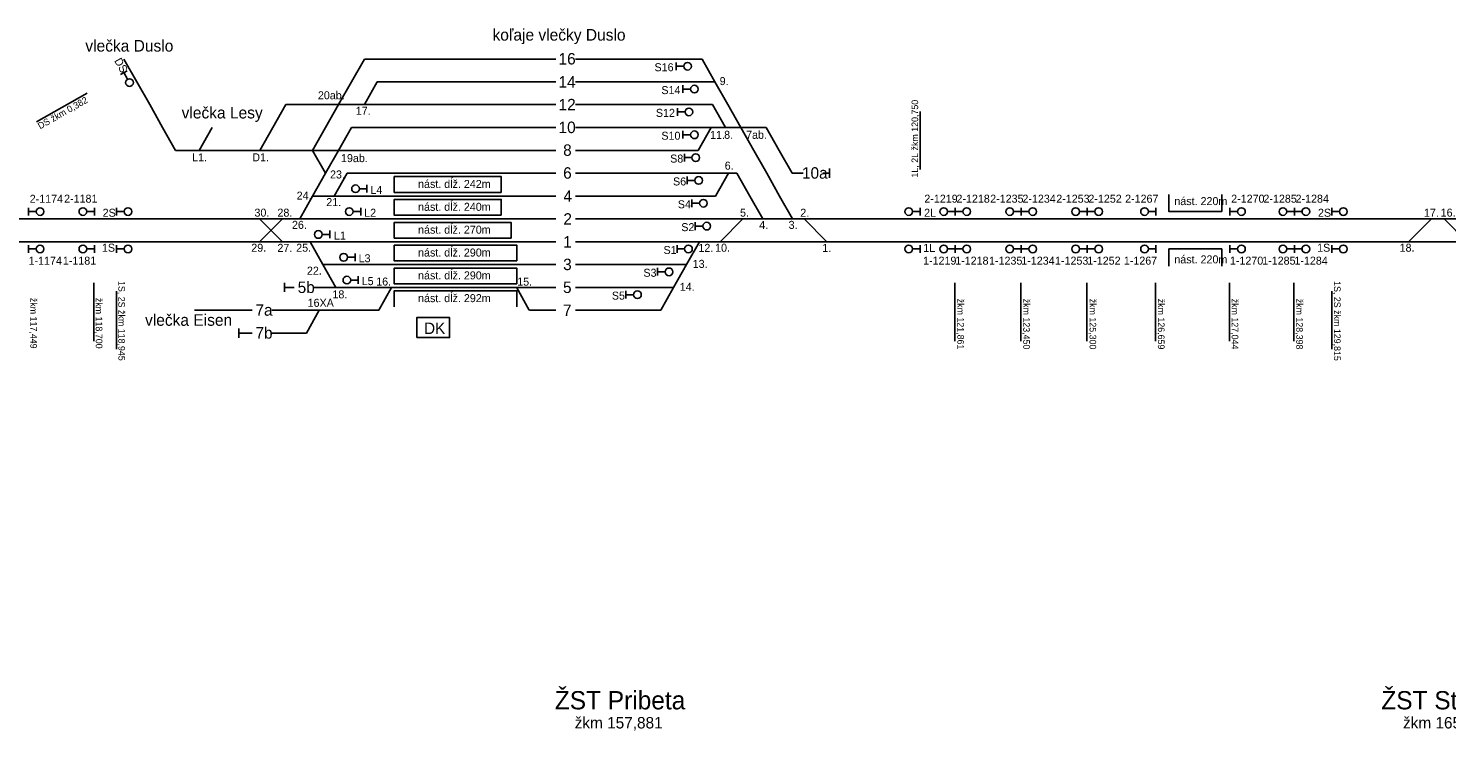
# Model space of a CAD drawing. Extents: x -119 to 851, y -238 to 59.
# Drawn here: x 119.9 to 243.9, y -152.1 to -90.6 of the extents above; entities that cross this region are included whole.
import ezdxf

# ---------------------------------------------------------------- set-up
doc = ezdxf.new("R2010")
doc.units = 0
for name, color, linetype in [('budova', 7, 'Continuous'), ('Level 2', 7, 'Continuous'), ('nastupistia', 7, 'Continuous'), ('netlač', 7, 'Continuous'), ('popisky navestidla', 7, 'Continuous'), ('popisky stanic a zastavok', 7, 'Continuous'), ('PU_navestidla', 7, 'Continuous'), ('PU_oznacenie navestidiel', 7, 'Continuous'), ('PU_stan_kolaje', 7, 'Continuous'), ('PU_vlecky', 7, 'Continuous')]:
    doc.layers.add(name, color=color, linetype=linetype)

msp = doc.modelspace()

# ---------------------------------------------------------------- linework, layer by layer
at = {"layer": 'budova'}
msp.add_lwpolyline([(153.86, -117.69), (156.73, -117.69), (156.73, -115.94), (153.86, -115.94)], close=True, dxfattribs=at)
at = {"layer": 'Level 2'}
for p, q in [((189.96, -103.71), (189.96, -102.91)), ((144.75, -105.31), (166.03, -105.31)), ((167.75, -105.31), (179.98, -105.31)), ((127.6, -107.3), (134.86, -107.3)), ((134.86, -107.3), (151.05, -107.3)), ((151.05, -107.3), (166.03, -107.3)), ((167.75, -107.3), (174.65, -107.3)), ((174.65, -107.3), (197.85, -107.3)), ((233.89, -107.3), (243.69, -107.3)), ((243.69, -107.3), (259.89, -107.3)), ((127.6, -109.3), (149.85, -109.3)), ((149.85, -109.3), (166.03, -109.3)), ((167.75, -109.3), (175.65, -109.3)), ((175.65, -109.3), (193.95, -109.3)), ((193.95, -109.3), (197.85, -109.3)), ((233.89, -109.3), (258.69, -109.3)), ((145.65, -111.3), (166.03, -111.3)), ((167.75, -111.3), (177.45, -111.3)), ((142.3, -113.7), (142.3, -112.9)), ((167.75, -113.3), (176.32, -113.3)), ((167.75, -115.3), (175.19, -115.3)), ((138.29, -117.7), (138.29, -116.9))]:
    msp.add_line(p, q, dxfattribs=at)
at = {"layer": 'nastupistia'}
for points in [[(161.24, -104.99), (151.89, -104.99), (151.89, -103.61), (161.24, -103.61)], [(161.25, -106.99), (151.89, -106.99), (151.89, -105.61), (161.25, -105.61)], [(162.11, -108.99), (151.89, -108.99), (151.89, -107.61), (162.11, -107.61)], [(162.61, -110.99), (151.89, -110.99), (151.89, -109.61), (162.61, -109.61)], [(162.6, -112.99), (151.89, -112.99), (151.89, -111.61), (162.6, -111.61)]]:
    msp.add_lwpolyline(points, close=True, dxfattribs=at)
for points in [[(219.64, -105.17), (219.64, -106.67), (224.27, -106.67), (224.27, -105.17)], [(219.64, -111.44), (219.64, -109.94), (224.27, -109.94), (224.27, -111.44)], [(151.89, -114.99), (151.89, -113.6), (162.61, -113.6), (162.61, -114.99)]]:
    msp.add_lwpolyline(points, dxfattribs=at)
at = {"layer": 'netlač'}
for p, q in [((149.27, -93.32), (166.03, -93.32)), ((178.81, -93.32), (167.75, -93.32)), ((150.4, -95.31), (166.03, -95.31)), ((179.94, -95.31), (167.75, -95.31)), ((149.27, -97.31), (142.4, -97.31)), ((149.27, -97.31), (166.03, -97.31)), ((179.72, -97.31), (167.75, -97.31)), ((148.14, -99.31), (166.03, -99.31)), ((182.2, -99.31), (167.75, -99.31)), ((182.2, -99.31), (184.42, -99.31)), ((147.01, -101.31), (132.76, -101.31)), ((147.01, -101.31), (166.03, -101.31)), ((178.47, -101.31), (167.75, -101.31)), ((147.76, -103.31), (166.03, -103.31)), ((181.86, -103.31), (167.75, -103.31)), ((186.68, -103.31), (187.64, -103.31)), ((189.36, -103.31), (189.96, -103.31)), ((127.6, -107.3), (113.86, -107.3)), ((233.89, -107.3), (197.85, -107.3)), ((127.6, -109.3), (113.86, -109.3)), ((233.89, -109.3), (197.85, -109.3)), ((143.13, -113.3), (142.3, -113.3)), ((146.78, -113.3), (144.85, -113.3)), ((146.78, -113.3), (166.03, -113.3)), ((138.29, -115.3), (134.42, -115.3)), ((139.45, -115.3), (138.29, -115.3)), ((147.53, -115.3), (141.18, -115.3)), ((150.53, -115.3), (147.53, -115.3)), ((163.71, -115.3), (166.03, -115.3)), ((139.45, -117.3), (138.29, -117.3)), ((144.2, -117.3), (141.18, -117.3))]:
    msp.add_line(p, q, dxfattribs=at)
at = {"layer": 'popisky navestidla'}
for p, q in [((125.03, -96.31), (120.6, -98.82)), ((197.9, -102.99), (197.9, -97.9)), ((125.62, -112.91), (125.62, -118)), ((127.6, -113.62), (127.6, -118.71)), ((200.92, -112.9), (200.92, -118)), ((206.69, -112.9), (206.69, -118)), ((212.46, -112.9), (212.46, -118)), ((218.48, -112.9), (218.48, -118)), ((224.95, -112.9), (224.95, -118)), ((230.58, -112.9), (230.58, -118)), ((233.89, -113.62), (233.89, -118.71))]:
    msp.add_line(p, q, dxfattribs=at)
at = {"layer": 'PU_navestidla'}
for p, q in [((176.53, -94.29), (176.53, -93.62)), ((176.53, -93.95), (177.2, -93.95)), ((127.94, -94.67), (128.52, -94.34)), ((128.23, -94.5), (128.56, -95.09)), ((177.13, -96.29), (177.13, -95.61)), ((177.13, -95.95), (177.81, -95.95)), ((176.65, -98.28), (176.65, -97.61)), ((176.65, -97.95), (177.32, -97.95)), ((177.13, -100.28), (177.13, -99.61)), ((177.13, -99.95), (177.81, -99.95)), ((177.26, -102.28), (177.26, -101.61)), ((177.26, -101.94), (177.93, -101.94)), ((177.5, -104.28), (177.5, -103.61)), ((177.5, -103.94), (178.17, -103.94)), ((149.5, -104.67), (148.83, -104.67)), ((149.5, -104.33), (149.5, -105.01)), ((119.9, -106.34), (119.9, -107.01)), ((119.9, -106.67), (120.57, -106.67)), ((125.66, -106.67), (124.99, -106.67)), ((125.66, -106.34), (125.66, -107.01)), ((127.6, -106.33), (127.6, -107)), ((127.6, -106.67), (128.27, -106.67)), ((148.96, -106.67), (148.28, -106.67)), ((148.96, -106.33), (148.96, -107)), ((177.92, -106.28), (177.92, -105.61)), ((177.92, -105.94), (178.6, -105.94)), ((197.9, -106.67), (197.22, -106.67)), ((197.9, -106.33), (197.9, -107)), ((200.96, -106.67), (200.28, -106.67)), ((200.96, -106.33), (200.96, -107.01)), ((200.96, -106.33), (200.96, -107.01)), ((200.96, -106.67), (201.63, -106.67)), ((206.72, -106.67), (206.05, -106.67)), ((206.72, -106.33), (206.72, -107.01)), ((206.72, -106.33), (206.72, -107.01)), ((206.72, -106.67), (207.4, -106.67)), ((212.49, -106.67), (211.82, -106.67)), ((212.49, -106.33), (212.49, -107.01)), ((212.49, -106.33), (212.49, -107.01)), ((212.49, -106.67), (213.17, -106.67)), ((218.51, -106.67), (217.84, -106.67)), ((218.51, -106.33), (218.51, -107.01)), ((224.98, -106.33), (224.98, -107.01)), ((224.98, -106.67), (225.65, -106.67)), ((230.62, -106.67), (229.94, -106.67)), ((230.62, -106.33), (230.62, -107.01)), ((230.62, -106.33), (230.62, -107.01)), ((230.62, -106.67), (231.29, -106.67)), ((233.89, -106.33), (233.89, -107)), ((233.89, -106.67), (234.57, -106.67)), ((178.22, -108.28), (178.22, -107.6)), ((146.25, -108.67), (145.58, -108.67)), ((146.25, -108.33), (146.25, -109)), ((178.22, -107.94), (178.89, -107.94)), ((119.9, -110.28), (119.9, -109.61)), ((119.9, -109.94), (120.57, -109.94)), ((125.66, -109.94), (124.99, -109.94)), ((125.66, -110.28), (125.66, -109.61)), ((127.6, -110.28), (127.6, -109.61)), ((127.6, -109.94), (128.27, -109.94)), ((148.47, -110.33), (148.47, -111)), ((176.62, -110.28), (176.62, -109.6)), ((176.62, -109.94), (177.29, -109.94)), ((197.9, -109.94), (197.22, -109.94)), ((197.9, -110.28), (197.9, -109.6)), ((200.96, -109.94), (200.28, -109.94)), ((200.96, -110.28), (200.96, -109.6)), ((200.96, -110.28), (200.96, -109.6)), ((200.96, -109.94), (201.63, -109.94)), ((206.72, -109.94), (206.05, -109.94)), ((206.72, -110.28), (206.72, -109.6)), ((206.72, -110.28), (206.72, -109.6)), ((206.72, -109.94), (207.4, -109.94)), ((212.49, -109.94), (211.82, -109.94)), ((212.49, -110.28), (212.49, -109.6)), ((212.49, -110.28), (212.49, -109.6)), ((212.49, -109.94), (213.17, -109.94)), ((218.51, -109.94), (217.84, -109.94)), ((218.51, -110.28), (218.51, -109.6)), ((224.98, -110.28), (224.98, -109.6)), ((224.98, -109.94), (225.65, -109.94)), ((230.62, -109.94), (229.94, -109.94)), ((230.62, -110.28), (230.62, -109.6)), ((230.62, -110.28), (230.62, -109.6)), ((230.62, -109.94), (231.29, -109.94)), ((233.89, -110.28), (233.89, -109.61)), ((233.89, -109.94), (234.57, -109.94)), ((148.47, -110.67), (147.8, -110.67)), ((174.91, -112.27), (174.91, -111.6)), ((148.74, -112.67), (148.07, -112.67)), ((148.74, -112.33), (148.74, -113)), ((174.91, -111.94), (175.58, -111.94)), ((172.15, -114.27), (172.15, -113.6)), ((172.15, -113.94), (172.82, -113.94))]:
    msp.add_line(p, q, dxfattribs=at)
for centre in [(177.54, -93.95), (128.73, -95.38), (178.14, -95.95), (177.66, -97.95), (178.14, -99.95), (178.26, -101.95), (178.51, -103.94), (148.5, -104.67), (120.91, -106.67), (124.65, -106.67), (128.6, -106.67), (147.95, -106.67), (178.93, -105.94), (196.89, -106.67), (199.95, -106.67), (201.96, -106.67), (205.72, -106.67), (207.73, -106.67), (211.49, -106.67), (213.5, -106.67), (217.51, -106.67), (225.99, -106.67), (229.61, -106.67), (231.62, -106.67), (234.9, -106.67), (179.22, -107.94), (145.25, -108.67), (120.91, -109.94), (124.65, -109.94), (128.6, -109.94), (147.46, -110.67), (177.62, -109.94), (196.89, -109.94), (199.95, -109.94), (201.96, -109.94), (205.72, -109.94), (207.73, -109.94), (211.49, -109.94), (213.5, -109.94), (217.51, -109.94), (225.99, -109.94), (229.61, -109.94), (231.62, -109.94), (234.9, -109.94), (175.92, -111.94), (147.74, -112.66), (173.16, -113.94)]:
    msp.add_circle(centre, 0.336, dxfattribs=at)
at = {"layer": 'PU_stan_kolaje'}
for points in [[(128.24, -93.32), (129.37, -95.31)], [(148.14, -95.32), (149.27, -93.32)], [(178.81, -93.32), (179.94, -95.31)], [(129.37, -95.31), (130.5, -97.31)], [(147.01, -97.31), (148.14, -95.32)], [(149.27, -97.31), (150.4, -95.31)], [(179.94, -95.31), (181.07, -97.31)], [(130.5, -97.31), (131.63, -99.31)], [(141.27, -99.31), (142.4, -97.31)], [(145.88, -99.31), (147.01, -97.31)], [(179.72, -97.31), (180.85, -99.31)], [(181.07, -97.31), (182.2, -99.31)], [(131.63, -99.31), (132.76, -101.31)], [(134.82, -101.31), (135.95, -99.31)], [(140.14, -101.31), (141.27, -99.31)], [(144.75, -101.31), (145.88, -99.31)], [(147.01, -101.31), (148.14, -99.31)], [(178.47, -101.31), (179.6, -99.31)], [(182.2, -99.31), (183.33, -101.31)], [(184.42, -99.31), (185.55, -101.31)], [(145.88, -103.31), (144.75, -101.31)], [(145.88, -103.31), (147.01, -101.31)], [(183.33, -101.31), (184.46, -103.31)], [(185.55, -101.31), (186.68, -103.31)], [(144.75, -105.31), (145.88, -103.31)], [(146.63, -105.31), (147.76, -103.31)], [(179.98, -105.31), (181.11, -103.31)], [(181.86, -103.31), (182.99, -105.31)], [(184.46, -103.31), (185.59, -105.31)], [(143.62, -107.3), (144.75, -105.31)], [(182.99, -105.31), (184.12, -107.3)], [(185.59, -105.31), (186.72, -107.3)], [(142.11, -107.3), (140.11, -109.3)], [(140.11, -107.3), (142.11, -109.3)], [(182.38, -107.3), (180.38, -109.3)], [(187.73, -107.3), (189.73, -109.3)], [(242.61, -107.3), (240.61, -109.3)], [(243.71, -107.3), (245.71, -109.3)], [(144.52, -109.3), (145.65, -111.3)], [(177.45, -111.3), (178.58, -109.3)], [(145.65, -111.3), (146.78, -113.3)], [(176.32, -113.3), (177.45, -111.3)], [(150.53, -115.3), (151.66, -113.3)], [(162.57, -113.28), (163.7, -115.28)], [(175.19, -115.3), (176.32, -113.3)], [(144.2, -117.3), (145.33, -115.3)]]:
    msp.add_lwpolyline(points, dxfattribs=at)

# ---------------------------------------------------------------- texts
at = {"layer": 'budova'}
msp.add_text('DK', height=1.004, dxfattribs=at).set_placement((154.49, -117.38))
at = {"layer": 'nastupistia'}
for s, p in [('nást. dĺž. 242m', (153.97, -104.6)), ('nást. 220m', (220.12, -106.1)), ('nást. dĺž. 240m', (153.97, -106.6)), ('nást. dĺž. 270m', (153.97, -108.6)), ('nást. dĺž. 290m', (153.97, -110.6)), ('nást. 220m', (220.12, -111.2)), ('nást. dĺž. 290m', (153.97, -112.6)), ('nást. dĺž. 292m', (153.97, -114.59))]:
    msp.add_text(s, height=0.7, dxfattribs=at).set_placement(p)
at = {"layer": 'popisky navestidla'}
for s, rotation, p in [('DS žkm 0,382', 29.4842, (120.91, -99.48)), ('1L, 2L žkm 120,750', 90, (197.71, -103.69)), ('1S, 2S žkm 118,945', 270, (127.76, -112.74)), ('1S, 2S žkm 129,815', 270, (234.08, -112.75)), ('žkm 117,449', 270, (120.06, -114.22)), ('žkm 118,700', 270, (125.78, -114.22)), ('žkm 121,861', 270, (201.14, -114.29)), ('žkm 123,450', 270, (206.9, -114.29)), ('žkm 125,300', 270, (212.7, -114.29)), ('žkm 126,659', 270, (218.68, -114.29)), ('žkm 127,044', 270, (225.13, -114.29)), ('žkm 128,398', 270, (230.78, -114.29))]:
    msp.add_text(s, height=0.5793, rotation=rotation, dxfattribs=at).set_placement(p)
at = {"layer": 'popisky stanic a zastavok'}
for s, height, p in [('ŽST Pribeta', 1.6, (165.93, -150.22)), ('ŽST Strekov', 1.6, (238.22, -150.22)), ('žkm 157,881', 1.0044, (167.67, -151.89)), ('žkm 165,420', 1.0044, (240.12, -151.89))]:
    msp.add_text(s, height=height, dxfattribs=at).set_placement(p)
at = {"layer": 'PU_oznacenie navestidiel'}
msp.add_text('DS', height=0.7, rotation=299.4842, dxfattribs=at).set_placement((127.37, -93.47))
for s, p in [('S16', (174.65, -94.39)), ('9.', (180.35, -95.6)), ('20ab.', (145.21, -96.84)), ('S14', (175.25, -96.39)), ('17.', (148.52, -98.2)), ('S12', (174.77, -98.38)), ('S10', (175.25, -100.38)), ('11.', (179.51, -100.31)), ('8.', (180.74, -100.3)), ('7ab.', (182.66, -100.3)), ('L1.', (134.21, -102.27)), ('D1.', (139.47, -102.27)), ('19ab.', (147.23, -102.34)), ('S8', (176.02, -102.38)), ('6.', (180.79, -103)), ('23.', (146.27, -103.77)), ('S6', (176.27, -104.38)), ('2-1174', (120, -105.9)), ('2-1181', (123.01, -105.89)), ('24.', (143.35, -105.62)), ('L4', (149.8, -105.12)), ('2-1219', (198.25, -105.89)), ('2-1218', (201.06, -105.89)), ('2-1235', (204.01, -105.89)), ('2-1234', (206.83, -105.89)), ('2-1253', (209.79, -105.89)), ('2-1252', (212.6, -105.89)), ('2-1267', (215.81, -105.89)), ('2-1270', (225.09, -105.89)), ('2-1285', (227.91, -105.89)), ('2-1284', (230.72, -105.89)), ('2S', (126.38, -107.12)), ('30.', (139.66, -107.11)), ('28.', (141.67, -107.11)), ('21.', (145.94, -106.19)), ('L2', (149.26, -107.12)), ('S4', (176.69, -106.38)), ('5.', (182.13, -107.11)), ('2.', (187.4, -107.12)), ('2L', (198.23, -107.12)), ('2S', (232.68, -107.12)), ('17.', (241.95, -107.12)), ('16.', (243.41, -107.11)), ('26.', (142.94, -108.18)), ('S2', (176.99, -108.38)), ('4.', (183.81, -108.19)), ('3.', (186.38, -108.18)), ('L1', (146.61, -109.12)), ('1S', (126.32, -110.18)), ('29.', (139.38, -110.18)), ('27.', (141.67, -110.19)), ('25.', (143.31, -110.18)), ('L3', (148.77, -111.1)), ('S1', (175.44, -110.38)), ('12.', (178.49, -110.19)), ('10.', (179.95, -110.18)), ('1.', (189.33, -110.19)), ('1L', (198.16, -110.19)), ('1S', (232.61, -110.18)), ('18.', (239.82, -110.18)), ('1-1174', (119.9, -111.32)), ('1-1181', (122.9, -111.31)), ('22.', (144.25, -112.19)), ('13.', (177.99, -111.59)), ('1-1219', (198.14, -111.31)), ('1-1218', (200.95, -111.31)), ('1-1235', (203.91, -111.31)), ('1-1234', (206.73, -111.31)), ('1-1253', (209.68, -111.31)), ('1-1252', (212.5, -111.31)), ('1-1267', (215.7, -111.31)), ('1-1270', (224.98, -111.31)), ('1-1285', (227.8, -111.31)), ('1-1284', (230.62, -111.31)), ('L5', (149.04, -113.1)), ('16.', (150.31, -113.14)), ('15.', (162.64, -113.15)), ('S3', (173.68, -112.37)), ('18.', (146.48, -114.26)), ('S5', (170.92, -114.37)), ('14.', (176.86, -113.6)), ('16XA', (144.31, -115))]:
    msp.add_text(s, height=0.7, dxfattribs=at).set_placement(p)
at = {"layer": 'PU_stan_kolaje'}
for s, height, p in [('16', 1.004, (166.26, -93.8)), ('14', 1.004, (166.26, -95.82)), ('12', 1.004, (166.26, -97.81)), ('10', 1.004, (166.26, -99.8)), ('8', 1, (166.66, -101.79)), ('6', 1, (166.66, -103.79)), ('10a', 1.004, (187.55, -103.79)), ('4', 1, (166.69, -105.81)), ('2', 1, (166.68, -107.81)), ('1', 1, (166.66, -109.81)), ('3', 1, (166.66, -111.79)), ('5b', 1.004, (143.44, -113.79)), ('5', 1, (166.65, -113.79)), ('7a', 1.004, (139.75, -115.78)), ('7', 1, (166.65, -115.8)), ('7b', 1.004, (139.75, -117.78))]:
    msp.add_text(s, height=height, dxfattribs=at).set_placement(p)
at = {"layer": 'PU_vlecky'}
for s, p in [('vlečka Duslo', (124.87, -92.67)), ('koľaje vlečky Duslo', (160.48, -91.71)), ('vlečka Lesy', (133.29, -98.52)), ('vlečka Eisen', (130.09, -116.66))]:
    msp.add_text(s, height=1.015, dxfattribs=at).set_placement(p)

doc.saveas('drawing.dxf')
